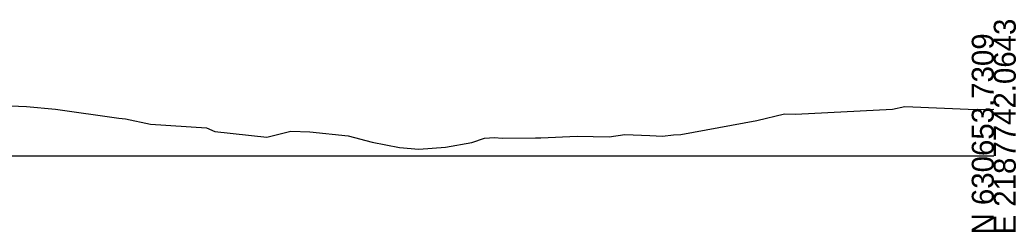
# Model space of a CAD drawing. Extents: x -26 to 4903, y -1010 to 9587.
# Drawn here: x 1176 to 1302.8, y 1990.3 to 2017.3 of the extents above; entities that cross this region are included whole.
import ezdxf

# ---------------------------------------------------------------- set-up
doc = ezdxf.new("R2010")
doc.units = 0
doc.layers.add('Exist Cross Section Cell', color=7, linetype='Continuous')
doc.layers.add('Exist XS Ground Line', color=7, linetype='Continuous')

msp = doc.modelspace()

# ---------------------------------------------------------------- linework, layer by layer
at = {"layer": 'Exist Cross Section Cell'}
msp.add_line((1150, 2000), (1300, 2000), dxfattribs=at)
at = {"layer": 'Exist XS Ground Line'}
for p, q in [((1173.85, 2006.42), (1176.89, 2006.3)), ((1176.89, 2006.3), (1180.55, 2005.94)), ((1180.55, 2005.94), (1188.65, 2004.8)), ((1274.77, 2005.3), (1287.1, 2005.96)), ((1287.1, 2005.96), (1288.69, 2006.29)), ((1288.69, 2006.29), (1297.78, 2005.91)), ((1297.78, 2005.91), (1300, 2005.97)), ((1188.65, 2004.8), (1189.5, 2004.72)), ((1189.5, 2004.72), (1192.66, 2004.03)), ((1269.86, 2004.53), (1273.37, 2005.37)), ((1273.37, 2005.37), (1274.77, 2005.3)), ((1192.66, 2004.03), (1199.81, 2003.58)), ((1199.81, 2003.58), (1200.86, 2003.11)), ((1260.17, 2002.73), (1269.86, 2004.53)), ((1200.86, 2003.11), (1207.49, 2002.4)), ((1207.49, 2002.4), (1210.53, 2003.14)), ((1210.53, 2003.14), (1212.95, 2003.07)), ((1212.95, 2003.07), (1217.81, 2002.55)), ((1217.81, 2002.55), (1220.89, 2001.75)), ((1233.56, 2001.73), (1235.16, 2002.28)), ((1235.16, 2002.28), (1236.44, 2002.33)), ((1236.44, 2002.33), (1237.42, 2002.28)), ((1237.42, 2002.28), (1241.65, 2002.29)), ((1241.65, 2002.29), (1242.33, 2002.31)), ((1242.33, 2002.31), (1246.98, 2002.5)), ((1246.98, 2002.5), (1251.04, 2002.44)), ((1251.04, 2002.44), (1253.06, 2002.75)), ((1253.06, 2002.75), (1256.23, 2002.59)), ((1256.23, 2002.59), (1257.83, 2002.52)), ((1257.83, 2002.52), (1259.23, 2002.7)), ((1259.23, 2002.7), (1260.17, 2002.73)), ((1220.89, 2001.75), (1224.37, 2001.08)), ((1224.37, 2001.08), (1226.82, 2000.85)), ((1226.82, 2000.85), (1230.2, 2001.1)), ((1230.2, 2001.1), (1233.56, 2001.73))]:
    msp.add_line(p, q, dxfattribs=at)

# ---------------------------------------------------------------- texts
at = {"layer": 'Exist Cross Section Cell'}
for s, p in [('E 2187742.0643', (1302.8, 1990)), ('N 630653.7309', (1300, 1990))]:
    msp.add_text(s, height=2.8, rotation=90, dxfattribs=at).set_placement(p)

doc.saveas('drawing.dxf')
